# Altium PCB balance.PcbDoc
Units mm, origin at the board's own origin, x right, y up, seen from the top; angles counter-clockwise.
Board outline 100 x 65 mm, 2 copper layers (Top Layer, Bottom Layer); 14 components, 19 nets, 113 pads, 4 vias.
Unrouted connection lines stored in the file: 2.
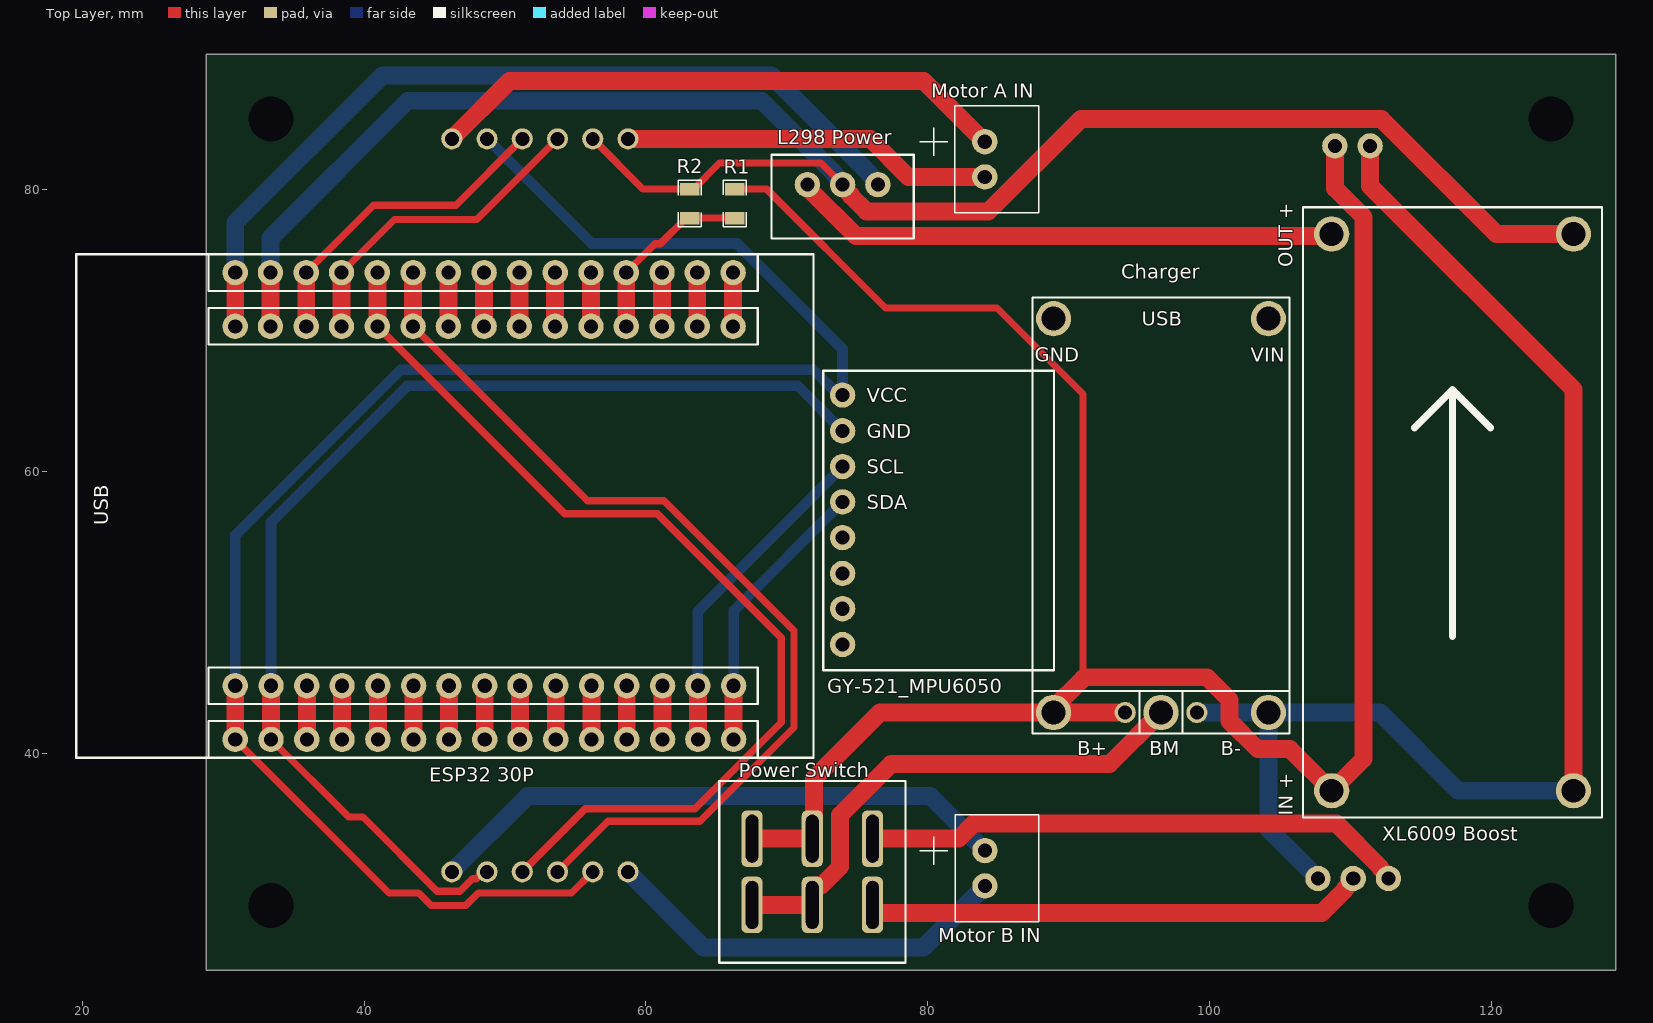
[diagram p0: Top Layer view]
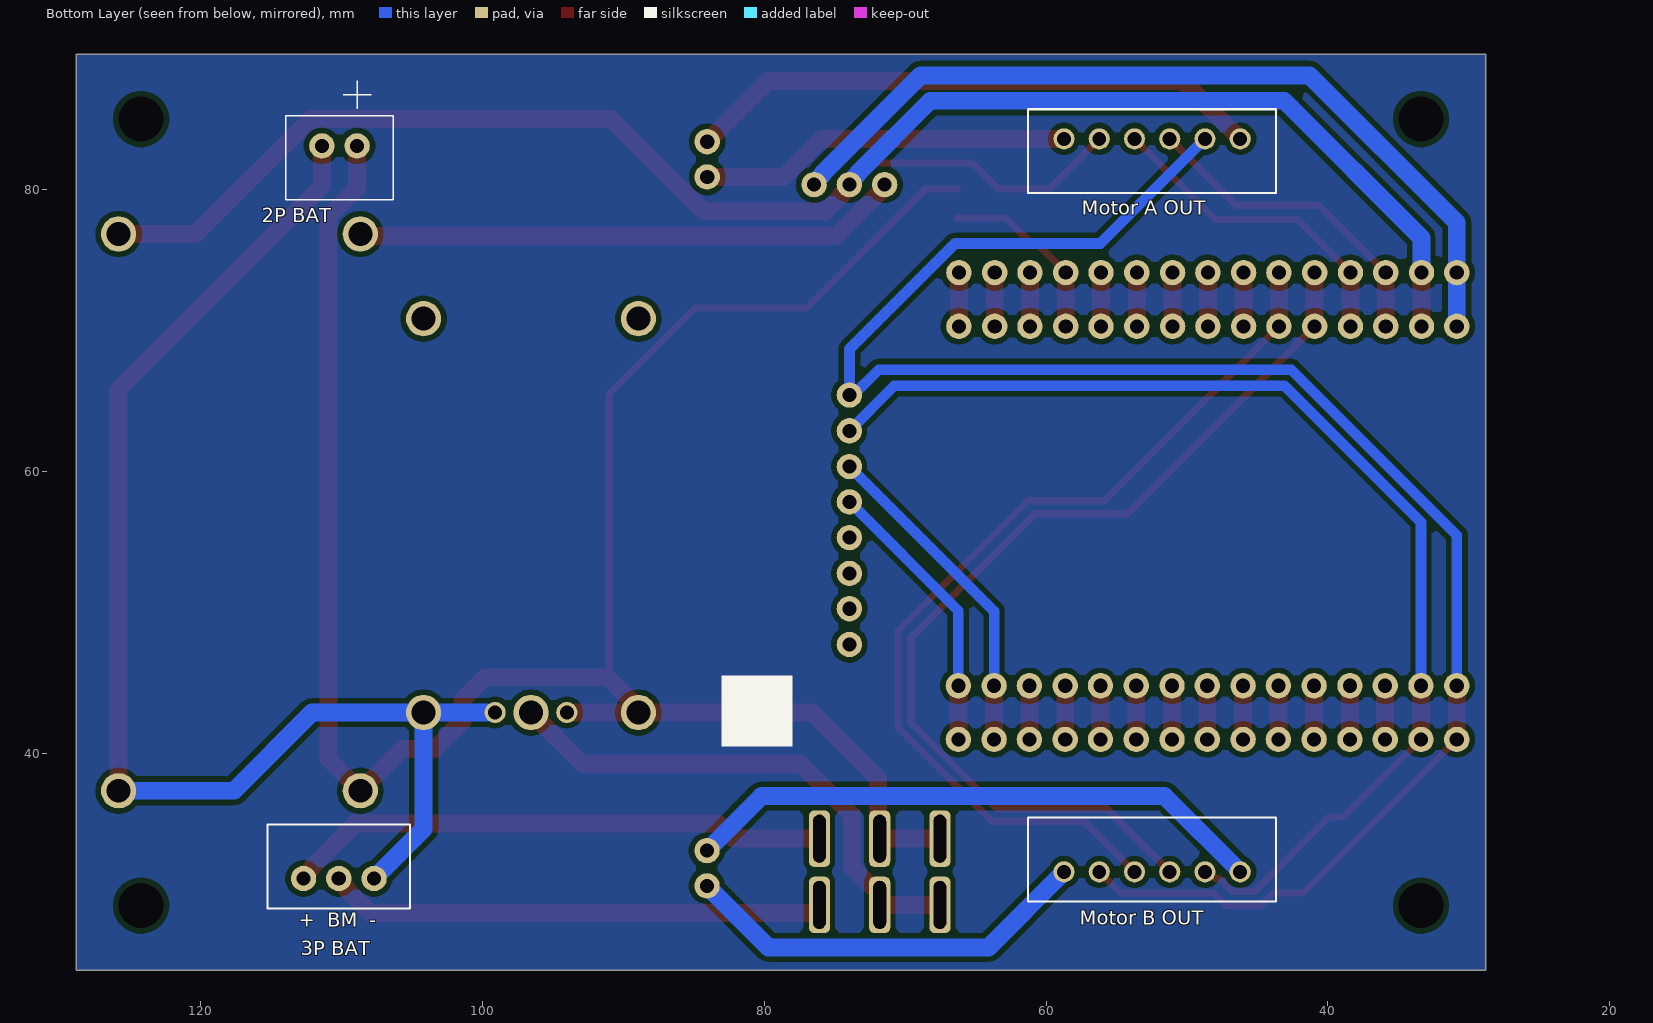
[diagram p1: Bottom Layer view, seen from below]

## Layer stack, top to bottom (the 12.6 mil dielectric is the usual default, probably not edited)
Top Solder: solder mask 0.0102, Solder Resist, Dk 3.5
Top Layer: signal copper 0.0356
Dielectric 1: dielectric 0.32, FR-4, Dk 4.8
Bottom Layer: signal copper 0.0356
Bottom Solder: solder mask 0.0102, Solder Resist, Dk 3.5

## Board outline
128.8,89.6 128.8,24.6 28.8,24.6 28.8,89.6

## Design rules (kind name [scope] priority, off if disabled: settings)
Clearance [All] p1: gap=0.381 ignorepadtopadclearanceinfootprint=TRUE
Height [All] p1: minheight=0 maxheight=250 prefheight=12.7
PolygonConnect [All] p1: connectstyle=Relief reliefconductorwidth=0.254 reliefentries=4 polygonreliefangle="90 Angle" airgapwidth=0.254
RoutingVias [All] p1: holewidth=0.711 width=1.27 viastyle="Through Hole" minholewidth=0.711 minwidth=1.27 maxholewidth=0.711 maxwidth=1.27
SolderMaskExpansion [All] p1: expansion=0.102 istentingtop=FALSE
SupplyNets "Schematic Supply Nets_2" [InNet('+5')] p1: voltage=0.000
SupplyNets "Schematic Supply Nets_1" [InNet('GND')] p2: voltage=0.000
SupplyNets "Schematic Supply Nets" [InNet('VCC')] p3: voltage=0.000
Width [All] p1: maxlimit=1.27 minlimit=0.381 preferedwidth=0.508
29 further rules are at their usual default settings.

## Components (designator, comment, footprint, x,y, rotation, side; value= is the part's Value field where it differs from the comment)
"2P BAT" "BatIN" BatIN 111.375,83.1 r0 bottom
"3P BAT" "BatIN3" BatIN3 107.675,31.125 r180 bottom
Charger "2S charger" 2S_charge 96.54,42.9 r0 top
"ESP32 30P" "ESP32_Dev_kit_V1_CH340_30P" ESP32 30.86,44.8 r90 top
GY-521_MPU6050 "GY-521_MPU6050" GY-521_MPU6050 80.6,56.4 r0 top
"L298 Power" "L298_Power" L298N_POWER 71.45,80.35 r180 top
"Motor A IN" "MotorOUT" MotorOUT 84.038,80.896 r270 top (schematic designator "Motor A IN?")
"Motor A OUT" "Motor" Motor 58.725,83.6 r0 bottom
"Motor B IN" "MotorOUT" MotorOUT 84.05,30.6 r270 top
"Motor B OUT" "Motor" Motor 46.225,31.6 r180 bottom
"Power Switch" "ON-OFF-ON" ON-OFF-ON 71.8,31.6 r180 top (schematic designator SWITCH?)
R1 "RES_0805_SMD" RES_0805_SMD 66.3,79 r270 top
R2 "RES_0805_SMD" RES_0805_SMD 63.1,79 r90 top
"XL6009 Boost" "XL6009" XL6009 117.223,57.099 r90 top

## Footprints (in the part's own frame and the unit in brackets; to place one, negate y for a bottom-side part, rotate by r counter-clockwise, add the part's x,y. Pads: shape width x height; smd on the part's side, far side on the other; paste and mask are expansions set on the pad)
2S_charge [mm]
  round 2.5 hole 1.7 paste-2539.97 mask+0: B+(-7.62,0) B-(7.62,0) BM(0,0) GND(-7.62,27.94) VIN(7.62,27.94)
  round 1.499 / inner round 1.524 / far side round 1.499 hole 0.991 paste-2539.97 mask+0: B+(-2.54,0) B-(2.54,0)
  silkscreen extent -9.12,-1.5 9.12,29.44, body extent -9.03,-1.5 8.98,30.9, height 12.95
BatIN [mm]
  round 1.8 hole 1 paste-2539.97 mask+0: +(-2.5,0) -(0,0)
  silkscreen extent -5.05,-4.62 2.55,3.83, body extent -4.95,-2.02 2.45,3.73, height 7
BatIN3 [mm]
  round 1.8 hole 1 paste-2539.97 mask+0: 0(0,0) 4.2(-2.5,0) 8.4(-5,0)
  silkscreen extent -7.55,-2.12 2.55,3.83, body extent -7.45,-2.03 2.45,3.72, height 7
ESP32 [mm]
  round 1.8 hole 1 paste-2539.97 mask+0: 3V3(-3.81,0) 3V3(0,0) D2(-3.81,-7.58) D2(0,-7.58) D4(-3.81,-10.12) D4(0,-10.12) D5(-3.81,-17.7) D5(0,-17.7) D12(25.5,-7.54) D12(29.31,-7.54) D13(25.5,-5.04) D13(29.31,-5.04) D14(25.5,-10.08) D14(29.31,-10.08) D15(-3.81,-5.08) D15(0,-5.08) D16(-3.81,-12.66) D16(0,-12.66) D17(-3.81,-15.16) D17(0,-15.16) D18(-3.81,-20.2) D18(0,-20.2) D19(-3.81,-22.74) D19(0,-22.74) D21(-3.81,-25.28) D21(0,-25.28) D22(-3.81,-32.82) D22(0,-32.82) D23(-3.81,-35.36) D23(0,-35.36) D25(25.5,-17.66) D25(29.31,-17.66) D26(25.5,-15.12) D26(29.31,-15.12) D27(25.5,-12.62) D27(29.31,-12.62) D32(25.5,-22.7) D32(29.31,-22.7) D33(25.5,-20.16) D33(29.31,-20.16) D34(25.5,-27.74) D34(29.31,-27.74) D35(25.5,-25.24) D35(29.31,-25.24) EN(25.5,-35.32) EN(29.31,-35.32) GND(-3.81,-2.54) GND(0,-2.54) GND(25.5,-2.5) GND(29.31,-2.5) RX0(-3.81,-27.78) RX0(0,-27.78) TX0(-3.81,-30.32) TX0(0,-30.32) Vin(25.5,0) Vin(29.31,0) VN(25.5,-30.28) VN(29.31,-30.28) VP(25.5,-32.78) VP(29.31,-32.78)
  silkscreen extent -5.11,-41.02 30.61,11.28, body extent -5.06,-40.84 30.46,11.26, height 16.1
GY-521_MPU6050 [mm]
  round 1.8 hole 1 paste-2539.97 mask+0: AD0(-6.65,-6.135) GND(-6.65,6.485) INT(-6.65,-8.675) SCL(-6.65,3.945) SDA(-6.65,1.445) VCC(-6.65,9.025) XCL(-6.65,-3.635) XDA(-6.65,-1.095)
  silkscreen extent -8.03,-10.5 8.35,10.75, body extent -7.93,-10.41 8.25,10.65, height 14.6
L298N_POWER [mm]
  round 1.8 hole 1 paste-2539.97 mask+0: 5V(-5,0) 12V(0,0) GND(-2.5,0)
  silkscreen extent -7.55,-2.12 2.55,3.83, body extent -7.45,-2.03 2.45,3.72, height 7
Motor [mil]
  round 59 / inner round 60 / far side round 59 hole 39 paste-99999 mask+0: "Encoder A"(-196.85,0) "Encoder B"(-295.28,0) GND(-98.43,0) M+(-492.13,0) M-(0,0) Vcc(-393.7,0)
  silkscreen extent -593,-83 100,152, body extent -589,-79 96,148, height 276
MotorOUT [mm]
  round 1.8 hole 1 paste-2539.97 mask+0: +(-2.5,0) -(0,0)
  silkscreen extent -5.05,-4.62 2.55,3.83, body extent -4.95,-2.02 2.45,3.73, height 7
ON-OFF-ON [mm]
  rrect50% 1.5x4 hole 0.9 slot 3.4 at 90 deg paste-2539.97 mask+0: OffA(0,2.35) OffB(0,-2.35) OnA1(-4.275,2.35) OnA2(4.275,2.35) OnB1(-4.275,-2.35) OnB2(4.275,-2.35)
  silkscreen extent -6.6,-6.45 6.6,6.45, body extent -6.5,-6.35 6.5,6.35, height 27.23
RES_0805_SMD [mil]
  rect 34x55 smd paste+0 mask+0: 1(-40.5,0) 2(40.5,0)
  silkscreen extent -65,-33 65,33, body extent -44,-27 44,27, height 20
XL6009 [mm]
  round 2.5 hole 1.7 paste-2539.97 mask+0: GND(-19.749,-8.573) GND(19.749,-8.573) VIN(-19.749,8.573) VOUT(19.749,8.573)
  silkscreen extent -21.65,-10.6 21.65,10.6, body extent -21.47,-10.48 21.72,10.6, height 20.75

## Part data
"Motor A OUT" "Motor B OUT": "Motor with encoder"
R1 R2: library part CMP-00003-7

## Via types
v1: diameter 1.27/1.27 (per signal layer), hole 3.2, Top Layer to Bottom Layer, 4 vias

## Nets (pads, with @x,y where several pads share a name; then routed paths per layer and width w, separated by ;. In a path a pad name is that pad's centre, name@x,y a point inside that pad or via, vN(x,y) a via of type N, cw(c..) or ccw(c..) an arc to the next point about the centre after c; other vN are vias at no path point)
+5: "ESP32 30P.Vin" "L298 Power.5V" | length 64.6
  Top Layer w1.27: 30.86,70.3 30.86,74.11
  Bottom Layer w1.27: 30.86,70.3 30.86,74.253 ; 30.86,74.11 30.86,77.66 41.3,88.1 68.91,88.1 75.866,81.144 75.866,81.077 76.45,80.493 76.45,80.35
GND: "2P BAT.-" "3P BAT.0" "ESP32 30P.GND" "L298 Power.GND" "Motor A OUT.GND" "Motor B OUT.GND" "XL6009 Boost.GND" Charger.B- GY-521_MPU6050.GND R2.2 | length 308.6
  Top Layer w0.508: 33.4,40.99 38.911,35.479 39.921,35.479 45.184,30.216 46.798,30.216 47.687,31.105 47.962,31.105 48.457,31.6 48.725,31.6 ; 56.225,83.6 59.796,80.029 R2.2 63.367,80.029 65.223,81.885 72.415,81.885 73.95,80.35
  Top Layer w1.27: 33.36,70.3 33.36,74.11 ; 33.4,40.99 33.4,44.8 ; 73.95,80.35 73.95,80.207 74.534,79.623 74.534,79.556 75.656,78.434 84.286,78.434 90.868,85.016 112.169,85.016 120.337,76.848 125.796,76.848 ; 111.375,83.1 111.375,80.251 125.796,65.83 125.796,37.35
  Bottom Layer w0.762: 33.4,44.8 33.4,56.4 43.075,66.075 70.76,66.075 GY-521_MPU6050.GND
  Bottom Layer w1.27: 33.36,74.11 33.36,76.56 43.1,86.3 68.21,86.3 73.366,81.144 73.366,81.077 73.95,80.493 73.95,80.35 ; Charger.B-@99.124,42.856 99.08,42.9 Charger.B-@104.16,42.9 ; 107.675,31.125 104.16,34.64 Charger.B-@104.16,42.9 ; 125.796,37.35 117.618,37.35 112.068,42.9 Charger.B-@104.16,42.9
"Net2P BAT_+": "2P BAT.+" "Power Switch.OffB" "Power Switch.OnB2" "XL6009 Boost.VIN" Charger.B+ R1.1 | length 156.2
  Top Layer w0.508: R1.1 68.571,80.029 77,71.6 84.9,71.6 91,65.5 91,45.3 ; Charger.B+@88.92,42.9 Charger.B+@88.92,43.22
  Top Layer w1.27: 67.525,33.95 71.8,33.95 71.915,34.065 71.915,38.215 76.6,42.9 88.92,42.9 Charger.B+@94,42.9 ; Charger.B+@88.92,43.22 91,45.3 91.1,45.4 99.8,45.4 101.4,43.8 101.4,42.3 103.4,40.3 105.7,40.3 108.65,37.35 110.916,39.616 110.916,78.049 108.875,80.09 108.875,83.1
"Net3P BAT_4.2": "3P BAT.4.2" "Power Switch.OnA1" | length 35.7
  Top Layer w1.27: 76.075,29.25 76.075,28.799 76.19,28.684 107.944,28.684 109.591,30.331 109.591,30.398 110.175,30.982 110.175,31.125
"Net3P BAT_8.4": "3P BAT.8.4" "Power Switch.OnB1" | length 38.8
  Top Layer w1.27: 76.075,33.95 82.19,33.95 83.256,35.016 108.994,35.016 112.091,31.919 112.091,31.852 112.675,31.268 112.675,31.125
NetCharger_BM: "Power Switch.OffA" "Power Switch.OnA2" Charger.BM | length 37.5
  Top Layer w1.27: 67.525,29.25 71.8,29.25 71.8,30.5 71.915,30.615 72.432,30.615 73.778,31.961 73.778,35.62 77.391,39.234 92.874,39.234 Charger.BM
"NetESP32 30P_D12": "ESP32 30P.D12" "Motor A OUT.Encoder A" | length 23.1
  Top Layer w0.508: 38.4,74.11 42.163,77.873 47.998,77.873 53.725,83.6
  Top Layer w1.27: 38.4,70.3 38.4,74.11
"NetESP32 30P_D13": "ESP32 30P.D13" "Motor A OUT.Encoder B" | length 23.1
  Top Layer w0.508: 35.9,74.11 40.679,78.889 46.514,78.889 51.225,83.6
  Top Layer w1.27: 35.9,70.3 35.9,74.11
"NetESP32 30P_D14": "ESP32 30P.D14" "Motor B OUT.Encoder A" | length 70.4
  Top Layer w0.508: 40.94,70.3 54.24,57 60.8,57 69.6,48.2 69.6,42.199 63.473,36.072 55.697,36.072 51.225,31.6
  Top Layer w1.27: 40.94,70.3 40.94,74.11
"NetESP32 30P_D22": "ESP32 30P.D22" GY-521_MPU6050.SCL | length 23.6
  Top Layer w1.27: 63.68,40.99 63.68,44.8
  Bottom Layer w0.762: 63.68,44.8 63.68,50.075 GY-521_MPU6050.SCL
"NetESP32 30P_D23": "ESP32 30P.D23" GY-521_MPU6050.SDA | length 20.1
  Top Layer w1.27: 66.22,40.99 66.22,44.8
  Bottom Layer w0.762: 66.22,44.8 66.22,50.115 GY-521_MPU6050.SDA
"NetESP32 30P_D27": "ESP32 30P.D27" "Motor B OUT.Encoder B" | length 67.7
  Top Layer w0.508: 43.48,70.3 55.857,57.923 61.277,57.923 70.5,48.7 70.5,41.842 63.841,35.183 57.308,35.183 53.725,31.6
  Top Layer w1.27: 43.48,70.3 43.48,74.11
"NetESP32 30P_D34": "ESP32 30P.D34" R1.2 R2.1 | length 13.1
  Top Layer w0.508: 58.6,74.11 60.642,76.152 61.014,76.152 62.833,77.971 R2.1 R1.2
  Top Layer w1.27: 58.6,70.3 58.6,74.11
"NetL298 Power_12V": "L298 Power.12V" "XL6009 Boost.VOUT" | length 38.9
  Top Layer w1.27: 71.45,80.35 71.551,80.249 71.551,80.039 74.89,76.7 108.502,76.7 108.65,76.848
"NetMotor A IN?_+": "Motor A IN.+" "Motor A OUT.M+" | length 41.3
  Top Layer w1.27: 46.225,83.6 46.228,83.6 50.328,87.7 79.706,87.7 84.01,83.396 84.038,83.396
"NetMotor A IN?_-": "Motor A IN.-" "Motor A OUT.M-" | length 26.4
  Top Layer w1.27: 58.725,83.6 75.91,83.6 78.614,80.896 84.038,80.896
"NetMotor B IN_+": "Motor B IN.+" "Motor B OUT.M-" | length 41.6
  Bottom Layer w1.27: 46.225,31.6 51.591,36.966 80.184,36.966 84.05,33.1
"NetMotor B IN_-": "Motor B IN.-" "Motor B OUT.M+" | length 29.4
  Bottom Layer w1.27: 58.725,31.6 64.091,26.234 79.684,26.234 84.05,30.6
VCC: "ESP32 30P.3V3" "Motor A OUT.Vcc" "Motor B OUT.Vcc" GY-521_MPU6050.VCC | length 129.1
  Top Layer w0.508: 30.86,40.99 41.761,30.089 43.874,30.089 44.763,29.2 47.219,29.2 48.108,30.089 54.714,30.089 56.225,31.6
  Top Layer w1.27: 30.86,40.99 30.86,44.8
  Bottom Layer w0.762: 30.86,44.8 30.86,55.476 42.602,67.218 71.876,67.218 73.669,65.425 GY-521_MPU6050.VCC 73.95,68.69 66.466,76.174 56.151,76.174 48.725,83.6
pads on no net: "ESP32 30P.D2" "ESP32 30P.D4" "ESP32 30P.D5" "ESP32 30P.D15" "ESP32 30P.D16" "ESP32 30P.D17" "ESP32 30P.D18" "ESP32 30P.D19" "ESP32 30P.D21" "ESP32 30P.D25" "ESP32 30P.D26" "ESP32 30P.D32" "ESP32 30P.D33" "ESP32 30P.D35" "ESP32 30P.EN" "ESP32 30P.RX0" "ESP32 30P.TX0" "ESP32 30P.VN" "ESP32 30P.VP" Charger.GND Charger.VIN GY-521_MPU6050.AD0 GY-521_MPU6050.INT GY-521_MPU6050.XCL GY-521_MPU6050.XDA
copper on no net: | length 72.4
  Top Layer w1.27: 35.94,40.99 35.94,44.8 ; 38.44,40.99 38.44,44.8 ; 40.98,40.99 40.98,44.8 ; 43.52,40.99 43.52,44.8 ; 45.98,70.3 45.98,74.11 ; 46.02,40.99 46.02,44.8 ; 48.52,70.3 48.52,74.11 ; 48.56,40.99 48.56,44.8 ; 51.02,70.3 51.02,74.11 ; 51.06,40.99 51.06,44.8 ; 53.56,70.3 53.56,74.11 ; 53.6,40.99 53.6,44.8 ; 56.1,70.3 56.1,74.11 ; 56.14,40.99 56.14,44.8 ; 58.64,40.99 58.64,44.8 ; 61.14,70.3 61.14,74.11 ; 61.18,40.99 61.18,44.8 ; 63.64,70.3 63.64,74.11 ; 66.18,70.3 66.18,74.11
  other v1: 33.4,29.2 124.2,29.2 33.4,85 124.2,85

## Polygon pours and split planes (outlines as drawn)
no net on Bottom Overlay (solid): 83,45.5 78,45.5 78,40.5 83,40.5
no net on Bottom Overlay (solid): 87,75 77,65
no net on Bottom Layer "Bottom Layer-No Net" (solid, pour order 0): 28.8,24.6 28.8,89.6 128.8,89.6 128.8,24.6

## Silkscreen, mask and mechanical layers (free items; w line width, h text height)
Bottom Solder:
  drawing of 1414 lines, arcs and shapes, not listed
Mechanical 2:
  circle w0.025: c33.396,29.195 r1.6
  circle w0.025: c124.196,84.995 r1.6
  circle w0.025: c124.196,84.995 r1.6
  circle w0.025: c33.396,84.995 r1.6
  circle w0.025: c33.396,29.195 r1.6
  circle w0.025: c124.196,29.195 r1.6
  circle w0.025: c124.196,29.195 r1.6
  circle w0.025: c33.396,84.995 r1.6
  circle w0.025: c78.796,64.595 r0.003
Mechanical 17:
  circle w0.013: c149.807,113.882 r0.013
  circle w0.013: c149.807,113.882 r0.013
  circle w0.006: c149.807,113.882 r0.003
  circle w0.013: c149.793,113.876 r0.013
  circle w0.013: c149.793,113.876 r0.013
  circle w0.006: c149.793,113.876 r0.003
  circle w0.013: c149.793,113.889 r0.013
  circle w0.013: c149.793,113.889 r0.013
  circle w0.006: c149.793,113.889 r0.003
  circle w0.013: c149.697,113.901 r0.013
  circle w0.013: c149.697,113.901 r0.013
  circle w0.006: c149.697,113.901 r0.003
  circle w0.013: c149.697,113.863 r0.013
  circle w0.013: c149.697,113.863 r0.013
  circle w0.006: c149.697,113.863 r0.003
  circle w0.013: c149.903,113.724 r0.013
  circle w0.013: c149.903,113.724 r0.013
  circle w0.006: c149.903,113.724 r0.003
  circle w0.013: c149.947,113.724 r0.013
  circle w0.013: c149.947,113.724 r0.013
  circle w0.006: c149.947,113.724 r0.003
  circle w0.013: c149.903,113.825 r0.013
  circle w0.013: c149.903,113.825 r0.013
  circle w0.006: c149.903,113.825 r0.003
  circle w0.013: c149.947,113.825 r0.013
  circle w0.013: c149.947,113.825 r0.013
  circle w0.006: c149.947,113.825 r0.003
Mechanical 18:
  circle w0.013: c149.997,113.864 r0.038
  circle w0.013: c149.997,113.864 r0.076
  circle w0.006: c149.997,113.864 r0.003
  circle w0.013: c149.997,113.723 r0.038
  circle w0.013: c149.997,113.723 r0.076
  circle w0.006: c149.997,113.723 r0.003
  circle w0.013: c149.998,113.746 r0.038
  circle w0.013: c149.998,113.746 r0.076
  circle w0.006: c149.998,113.746 r0.003
  circle w0.013: c149.998,113.841 r0.038
  circle w0.013: c149.998,113.841 r0.076
  circle w0.006: c149.998,113.841 r0.003
  circle w0.013: c149.904,113.746 r0.038
  circle w0.013: c149.904,113.746 r0.076
  circle w0.006: c149.904,113.746 r0.003
  circle w0.013: c149.904,113.841 r0.038
  circle w0.013: c149.904,113.841 r0.076
  circle w0.006: c149.904,113.841 r0.003
  circle w0.013: c149.845,113.864 r0.038
  circle w0.013: c149.845,113.864 r0.076
  circle w0.006: c149.845,113.864 r0.003
  circle w0.013: c149.845,113.723 r0.038
  circle w0.013: c149.845,113.723 r0.076
  circle w0.006: c149.845,113.723 r0.003
  circle w0.013: c149.614,113.864 r0.038
  circle w0.013: c149.614,113.864 r0.076
  circle w0.006: c149.614,113.864 r0.003
  circle w0.013: c149.614,113.723 r0.038
  circle w0.013: c149.614,113.723 r0.076
  circle w0.006: c149.614,113.723 r0.003
Mechanical 19:
  circle w0.013: c149.997,113.864 r0.051
  circle w0.006: c149.997,113.864 r0.003
  circle w0.013: c149.997,113.723 r0.051
  circle w0.006: c149.997,113.723 r0.003
  circle w0.013: c149.998,113.746 r0.051
  circle w0.006: c149.998,113.746 r0.003
  circle w0.013: c149.998,113.841 r0.051
  circle w0.006: c149.998,113.841 r0.003
  circle w0.013: c149.904,113.746 r0.051
  circle w0.006: c149.904,113.746 r0.003
  circle w0.013: c149.904,113.841 r0.051
  circle w0.006: c149.904,113.841 r0.003
  circle w0.013: c149.845,113.864 r0.051
  circle w0.006: c149.845,113.864 r0.003
  circle w0.013: c149.845,113.723 r0.051
  circle w0.006: c149.845,113.723 r0.003
  circle w0.013: c149.614,113.864 r0.051
  circle w0.006: c149.614,113.864 r0.003
  circle w0.013: c149.614,113.723 r0.051
  circle w0.006: c149.614,113.723 r0.003
Mechanical 20:
  circle w0.013: c149.98,113.813 r0.038
  circle w0.006: c149.98,113.813 r0.003
  circle w0.006: c149.98,113.813 r0.003
  circle w0.013: c149.98,113.772 r0.038
  circle w0.006: c149.98,113.772 r0.003
  circle w0.006: c149.98,113.772 r0.003
  circle w0.013: c149.945,113.813 r0.038
  circle w0.006: c149.945,113.813 r0.003
  circle w0.006: c149.945,113.813 r0.003
  circle w0.013: c149.945,113.772 r0.038
  circle w0.006: c149.945,113.772 r0.003
  circle w0.006: c149.945,113.772 r0.003
  circle w0.013: c149.667,113.815 r0.038
  circle w0.006: c149.667,113.815 r0.003
  circle w0.006: c149.667,113.815 r0.003
  circle w0.013: c149.667,113.774 r0.038
  circle w0.006: c149.667,113.774 r0.003
  circle w0.006: c149.667,113.774 r0.003
  circle w0.013: c149.631,113.815 r0.038
  circle w0.006: c149.631,113.815 r0.003
  circle w0.006: c149.631,113.815 r0.003
  circle w0.013: c149.631,113.774 r0.038
  circle w0.006: c149.631,113.774 r0.003
  circle w0.006: c149.631,113.774 r0.003
  circle w0.013: c149.904,113.841 r0.038
  circle w0.006: c149.904,113.841 r0.003
  circle w0.006: c149.904,113.841 r0.003
  circle w0.013: c149.904,113.746 r0.038
  circle w0.006: c149.904,113.746 r0.003
  circle w0.006: c149.904,113.746 r0.003
  circle w0.013: c149.614,113.864 r0.038
  circle w0.006: c149.614,113.864 r0.003
  circle w0.006: c149.614,113.864 r0.003
  circle w0.013: c149.614,113.723 r0.038
  circle w0.006: c149.614,113.723 r0.003
  circle w0.006: c149.614,113.723 r0.003
  circle w0.013: c149.997,113.864 r0.038
  circle w0.006: c149.997,113.864 r0.003
  circle w0.006: c149.997,113.864 r0.003
  circle w0.013: c149.997,113.723 r0.038
  circle w0.006: c149.997,113.723 r0.003
  circle w0.006: c149.997,113.723 r0.003
  circle w0.013: c149.845,113.723 r0.038
  circle w0.006: c149.845,113.723 r0.003
  circle w0.006: c149.845,113.723 r0.003
  circle w0.013: c149.845,113.864 r0.038
  circle w0.006: c149.845,113.864 r0.003
  circle w0.006: c149.845,113.864 r0.003
Mechanical 21:
  circle w0.013: c149.98,113.772 r0.038
  circle w0.013: c149.98,113.772 r0.076
  circle w0.006: c149.98,113.772 r0.003
  circle w0.013: c149.98,113.813 r0.038
  circle w0.013: c149.98,113.813 r0.076
  circle w0.006: c149.98,113.813 r0.003
  circle w0.013: c149.945,113.772 r0.038
  circle w0.013: c149.945,113.772 r0.076
  circle w0.006: c149.945,113.772 r0.003
  circle w0.013: c149.945,113.813 r0.038
  circle w0.013: c149.945,113.813 r0.076
  circle w0.006: c149.945,113.813 r0.003
  circle w0.013: c149.667,113.774 r0.038
  circle w0.013: c149.667,113.774 r0.076
  circle w0.006: c149.667,113.774 r0.003
  circle w0.013: c149.667,113.815 r0.038
  circle w0.013: c149.667,113.815 r0.076
  circle w0.006: c149.667,113.815 r0.003
  circle w0.013: c149.631,113.774 r0.038
  circle w0.013: c149.631,113.774 r0.076
  circle w0.006: c149.631,113.774 r0.003
  circle w0.013: c149.631,113.815 r0.038
  circle w0.013: c149.631,113.815 r0.076
  circle w0.006: c149.631,113.815 r0.003
Mechanical 22:
  circle w0.013: c149.98,113.772 r0.051
  circle w0.006: c149.98,113.772 r0.003
  circle w0.013: c149.98,113.813 r0.051
  circle w0.006: c149.98,113.813 r0.003
  circle w0.013: c149.945,113.772 r0.051
  circle w0.006: c149.945,113.772 r0.003
  circle w0.013: c149.945,113.813 r0.051
  circle w0.006: c149.945,113.813 r0.003
  circle w0.013: c149.667,113.774 r0.051
  circle w0.006: c149.667,113.774 r0.003
  circle w0.013: c149.667,113.815 r0.051
  circle w0.006: c149.667,113.815 r0.003
  circle w0.013: c149.631,113.774 r0.051
  circle w0.006: c149.631,113.774 r0.003
  circle w0.013: c149.631,113.815 r0.051
  circle w0.006: c149.631,113.815 r0.003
